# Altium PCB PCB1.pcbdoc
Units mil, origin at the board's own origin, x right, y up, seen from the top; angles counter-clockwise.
Board outline 7016.85 x 5604.57 mil, 2 copper layers (Top Layer, Bottom Layer); 46 components, 30 nets, 160 pads, 153 vias.
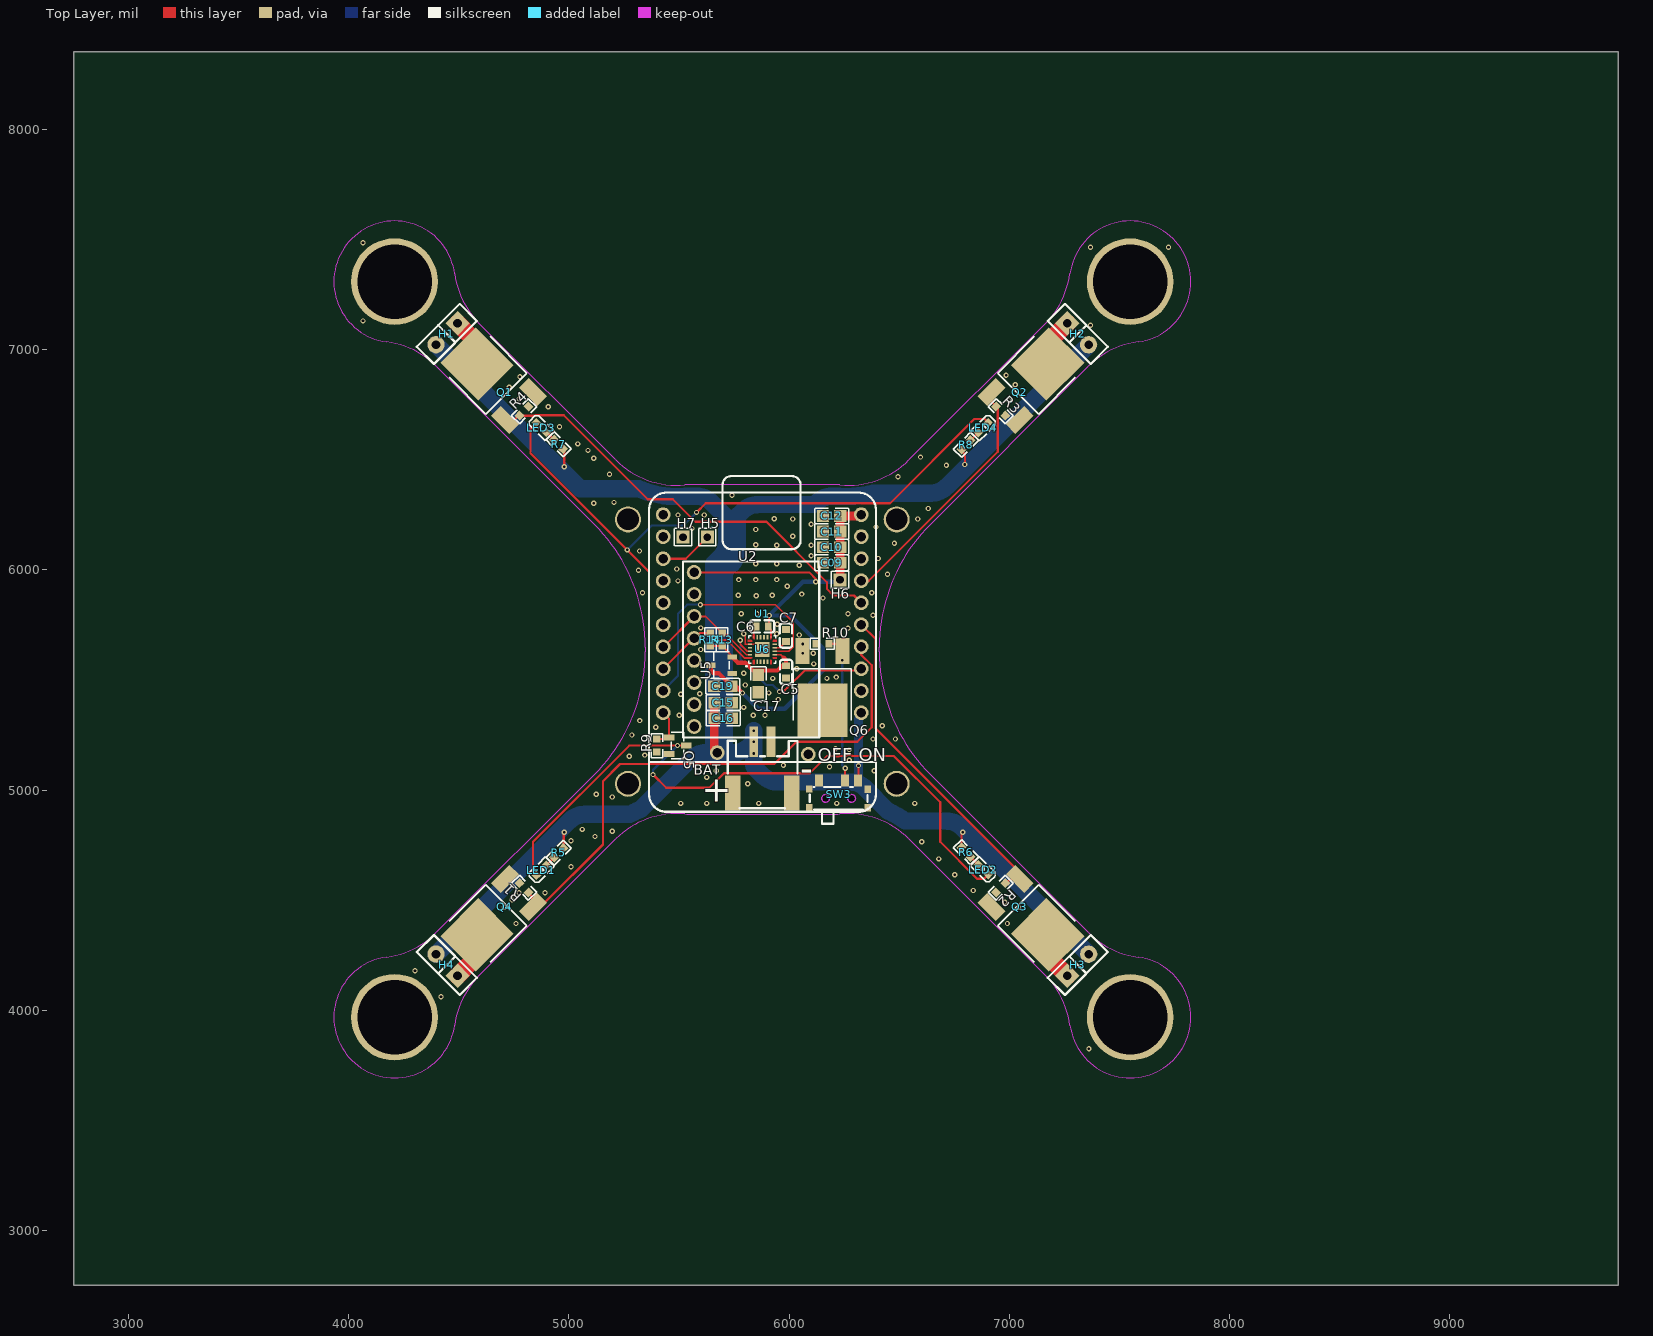
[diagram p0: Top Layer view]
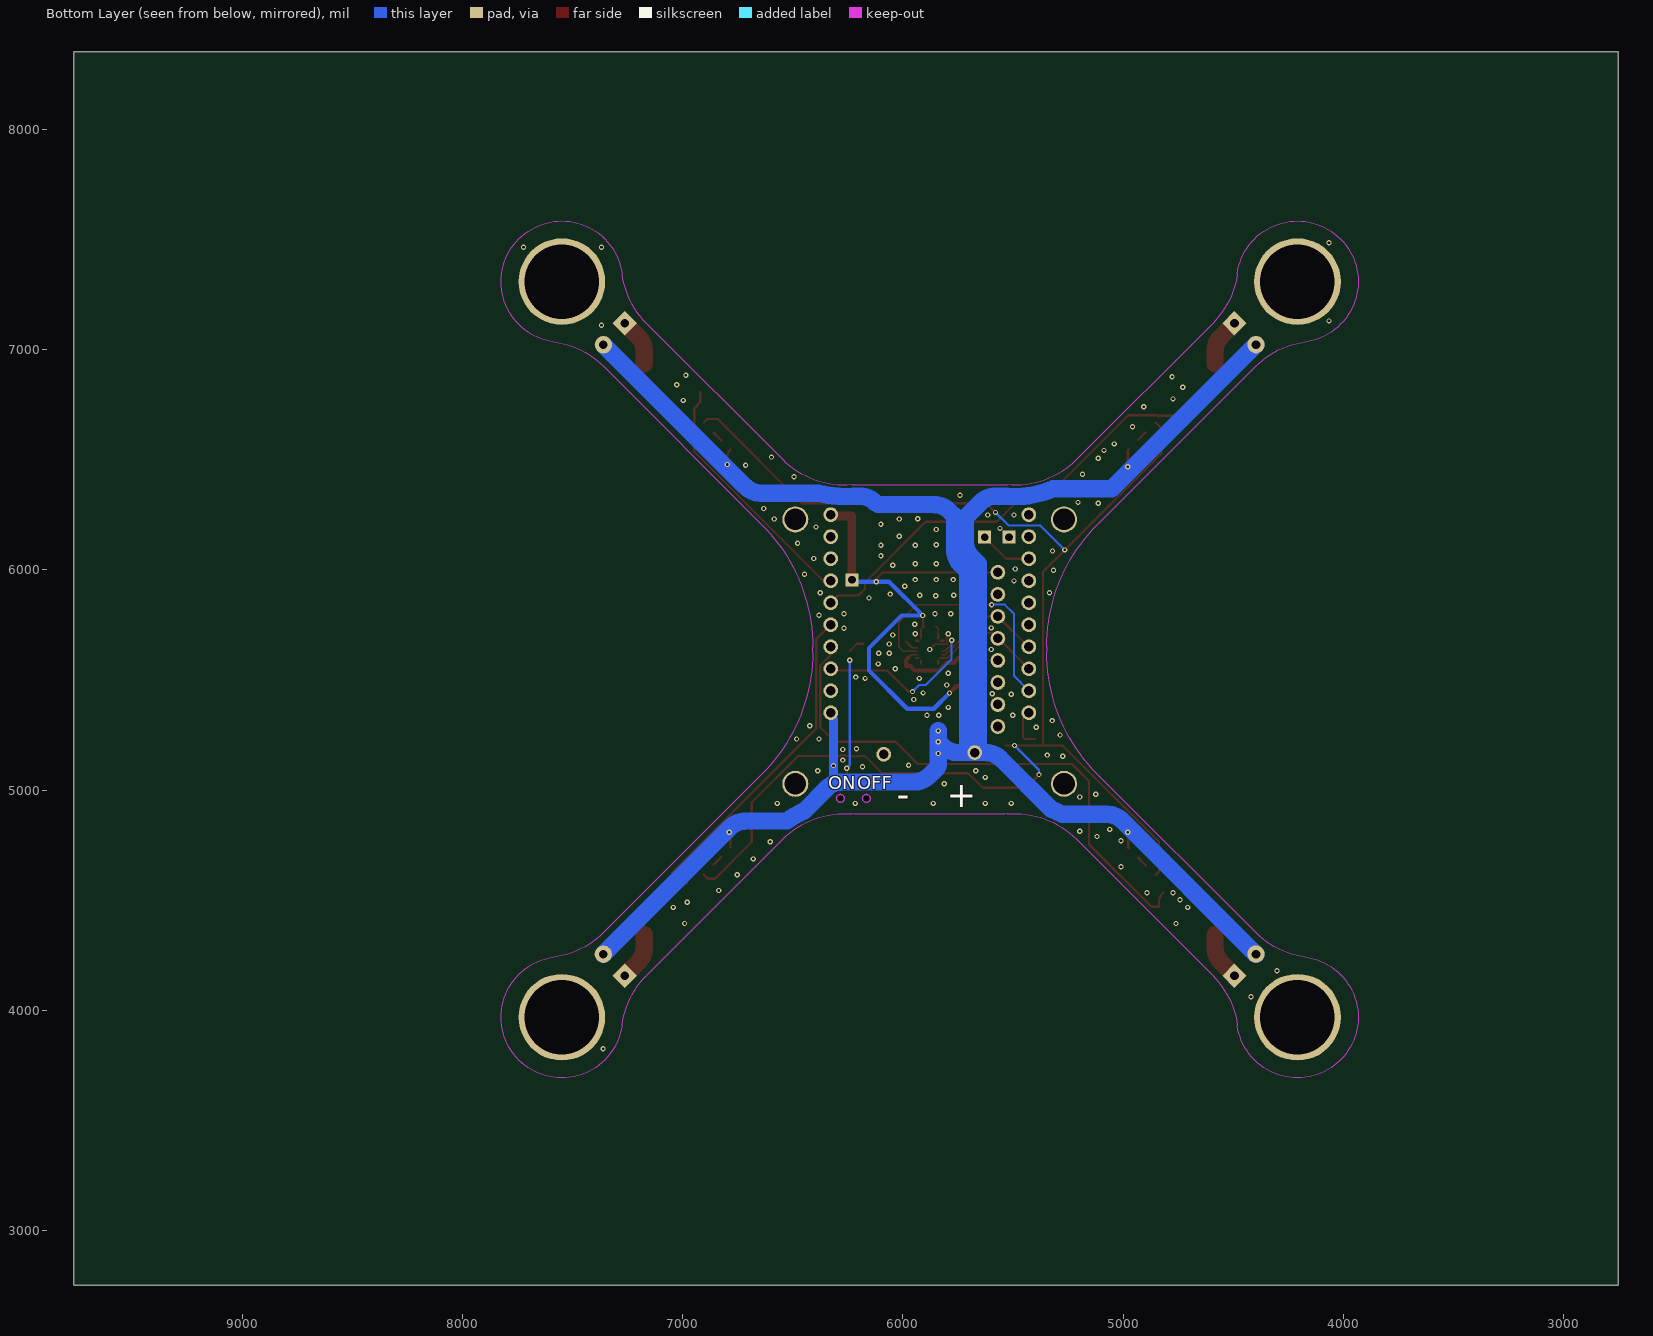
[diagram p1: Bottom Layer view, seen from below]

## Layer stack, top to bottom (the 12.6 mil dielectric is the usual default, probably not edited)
Top Layer: signal copper (thickness not stored)
Dielectric: dielectric 12.6, FR-4, Dk 4.8
Bottom Layer: signal copper (thickness not stored)

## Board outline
9766.85,2750 2750,2750 2750,8354.57 9766.85,8354.57

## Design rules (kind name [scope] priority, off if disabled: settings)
BoardOutlineClearance copperThickness1oz [All] p0: genericclearance=10 ignorepadtopadclearanceinfootprint=FALSE except(0: Arc-SplitContinuation Track-SplitContinuation SMDPad-SplitContinuation THPad-SplitContinuation Via-SplitContinuation Fill-SplitContinuation Poly-SplitContinuation Region-SplitContinuation Text-SplitContinuation; 6: Track-CutoutEdge SMDPad-CutoutEdge THPad-CutoutEdge Via-CutoutEdge Region-CutoutEdge; 11.8: Track-OutlineEdge SMDPad-OutlineEdge THPad-OutlineEdge Via-OutlineEdge Fill-OutlineEdge Region-OutlineEdge Poly-OutlineEdge Text-OutlineEdge Fill-CutoutEdge)
BoardOutlineClearance copperThickness2oz [All] p0: genericclearance=10 ignorepadtopadclearanceinfootprint=FALSE except(0: Arc-SplitContinuation Track-SplitContinuation SMDPad-SplitContinuation THPad-SplitContinuation Via-SplitContinuation Fill-SplitContinuation Poly-SplitContinuation Region-SplitContinuation Text-SplitContinuation; 6: Track-CutoutEdge SMDPad-CutoutEdge THPad-CutoutEdge Via-CutoutEdge Region-CutoutEdge; 11.8: Track-OutlineEdge SMDPad-OutlineEdge THPad-OutlineEdge Via-OutlineEdge Fill-OutlineEdge Region-OutlineEdge Poly-OutlineEdge Text-OutlineEdge Fill-CutoutEdge)
Clearance copperThickness1oz [(InNet('+VBAT') OR InNet('$1N990') OR InNet('$1N1042') OR InNet('$1N1143') OR InNet('$1N1147') OR InNet('GND') OR InNet('B-') OR InNet('+3.3V') OR InNet('SCL') OR InNet('SDA') OR InNet('P01') OR InNet('P05') OR InNet('P06') OR InNet('P04') OR InNet('P07') OR InNet('P08') OR InNet('P09') OR InNet('RX') OR InNet('$1N3735') OR InNet('$1N3774') OR InNet('$1N3813') OR InNet('$1N3852') OR InNet('$1N5655') OR InNet('$1N11155') OR InNet('$1N12497') OR InNet('1.8V') OR InNet('$2N590') OR InNet('P00') OR InNet('XDA') OR InNet('XCL'))] p1: gap=7 ignorepadtopadclearanceinfootprint=FALSE except(4: Track-Track; 6: Track-SMDPad SMDPad-SMDPad Track-THPad SMDPad-THPad THPad-THPad Track-Via SMDPad-Via THPad-Via Via-Via SMDPad-Fill THPad-Fill Via-Fill Fill-Fill Track-Region SMDPad-Region THPad-Region Via-Region Region-Region Track-Poly SMDPad-Poly THPad-Poly Via-Poly Fill-Poly Region-Poly Poly-Poly Track-Text SMDPad-Text THPad-Text Via-Text Fill-Text Region-Text Poly-Text Text-Text; 6.9: Track-Hole SMDPad-Hole THPad-Hole Via-Hole Fill-Hole Region-Hole Poly-Hole Text-Hole Sheet-Hole; 11.8: Track-Fill Fill-Region Track-Sheet SMDPad-Sheet THPad-Sheet Via-Sheet Fill-Sheet Region-Sheet Poly-Sheet Text-Sheet)
Clearance copperThickness2oz [All] p1: gap=7 ignorepadtopadclearanceinfootprint=FALSE except(6: Track-SMDPad SMDPad-SMDPad Track-THPad SMDPad-THPad THPad-THPad Track-Via SMDPad-Via THPad-Via Via-Via SMDPad-Fill THPad-Fill Via-Fill Fill-Fill Track-Region SMDPad-Region THPad-Region Via-Region Region-Region Track-Poly SMDPad-Poly THPad-Poly Via-Poly Fill-Poly Region-Poly Poly-Poly Track-Text SMDPad-Text THPad-Text Via-Text Fill-Text Region-Text Poly-Text Text-Text; 6.9: Track-Hole SMDPad-Hole THPad-Hole Via-Hole Fill-Hole Region-Hole Poly-Hole Text-Hole Sheet-Hole; 8: Track-Track; 11.8: Track-Fill Fill-Region Track-Sheet SMDPad-Sheet THPad-Sheet Via-Sheet Fill-Sheet Region-Sheet Poly-Sheet Text-Sheet)
DiffPairsRouting differentialPair [All] p1: maxuncoupledlength=10 minlimit=6 maxlimit=6 mostfreqgap=6 toplayer_minwidth=5 toplayer_prefwidth=10 toplayer_maxwidth=100 bottomlayer_minwidth=5 bottomlayer_prefwidth=10 bottomlayer_maxwidth=100
PasteMaskExpansion pasteMaskExpansion [All] p1: expansion=0
PlaneConnect innerPlane [All] p1: planeconnectstyle=Relief reliefexpansion=20 reliefentries=4 reliefconductorwidth=10 reliefairgap=10
PolygonConnect copperRegion [All] p1: connectstyle=Relief reliefentries=4 reliefconductorwidth=10 polygonreliefangle="90 Angle" airgapwidth=10
PolygonConnect solid [All] p1: connectstyle=Direct reliefentries=4 reliefconductorwidth=10 polygonreliefangle="90 Angle" airgapwidth=10
RoutingVias viaSize [All] p1: viastyle="Through Hole" holewidth=12.0078 minholewidth=11.811 maxholewidth=248.0314 width=24.0158 minwidth=19.685 maxwidth=393.7008
SolderMaskExpansion solderMaskExpansion [All] p1: useseparateexpansions=TRUE expansion=2 expansionbottom=2
Width copperThickness1oz [All] p1: maxlimit=100 minlimit=5 preferedwidth=10
Width copperThickness2oz [All] p1: maxlimit=100 minlimit=8 preferedwidth=10

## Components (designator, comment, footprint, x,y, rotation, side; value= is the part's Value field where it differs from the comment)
BAT "HX PH2.0-2PWT" CONN-SMD_2P-P2.00 5878.43,5103.62 r0 top
C5 "CC0603KRX7R9BB104" C0603 5986.14,5537.32 r90 top
C6 "CC0603KRX7R9BB104" C0603 5877.75,5743.69 r0 top
C7 "CC0603KRX7R9BB104" C0603 5985.46,5701.8 r270 top
C09 "JMK212BJ476MG-T" C0805 6193.39,6032.76 r0 top
C10 "JMK212BJ476MG-T" C0805 6193.39,6103.62 r0 top
C11 "JMK212BJ476MG-T" C0805 6193.39,6174.49 r0 top
C12 "JMK212BJ476MG-T" C0805 6193.39,6245.35 r0 top
C15 "JMK212BJ476MG-T" C0805 5700,5397.09 r180 top
C16 "JMK212BJ476MG-T" C0805 5700,5327.09 r180 top
C17 "JMK212BJ476MG-T" C0805 5860.47,5483.46 r90 top
C19 "JMK212BJ476MG-T" C0805 5698.9,5471.5 r0 top
H1 "KF332J-3.5-2P BLACK" HDR-TH_2P-P3.50-V-M_1 4445.35,7072.13 r225 top
H2 "KF332J-3.5-2P BLACK" HDR-TH_2P-P3.50-V-M_1 7311.5,7072.13 r315 top
H3 "KF332J-3.5-2P BLACK" HDR-TH_2P-P3.50-V-M_1 7311.5,4205.98 r45 top
H4 "KF332J-3.5-2P BLACK" HDR-TH_2P-P3.50-V-M_1 4445.35,4205.98 r135 top
H5 "TMM-101-01-G-S" HDR-TH_TMM-101-06-L-S 5628.43,6149.06 r0 top
H6 "TMM-101-01-G-S" HDR-TH_TMM-101-06-L-S 6231.42,5955.35 r0 top
H7 "TMM-101-01-G-S" HDR-TH_TMM-101-06-L-S 5518.43,6149.06 r0 top
LED1 "XL-1608SURC-06" LED0603-RD_RED 4874.64,4636.55 r45 top
LED2 "XL-1608SURC-06" LED0603-RD_RED 6882.36,4639.05 r135 top
LED3 "PSC-1608U50GC-G4" LED0603-RD_GREEN 4874.49,6646.93 r315 top
LED4 "PSC-1608U50GC-G4" LED0603-RD_GREEN 6882.36,6646.93 r225 top
Q1 "100N03A" TO-252-2_L6.6-W6.1-P4.57-LS9.9-BR-CW 4677.64,6839.84 r315 top
Q2 "100N03A" TO-252-2_L6.6-W6.1-P4.57-LS9.9-BR-CW 7079.21,6839.84 r225 top
Q3 "100N03A" TO-252-2_L6.6-W6.1-P4.57-LS9.9-BR-CW 7079.21,4438.27 r135 top
Q4 "100N03A" TO-252-2_L6.6-W6.1-P4.57-LS9.9-BR-CW 4677.64,4438.27 r45 top
Q5 "SI2302-HXY" SOT-23-3_L2.9-W1.3-P1.90-LS2.4-BR 5493.78,5202.45 r180 top
Q6 "100N03A" TO-252-2_L6.6-W6.1-P4.57-LS9.9-BR-CW 6151.57,5497.4 r90 top
R1 "0603WAF1002T5E" R0603 4795.75,4556.38 r135 top
R2 "0603WAF1002T5E" R0603 6961.1,4556.38 r225 top
R3 "0603WAF1002T5E" R0603 6961.1,6721.73 r315 top
R4 "0603WAF1002T5E" R0603 4795.75,6721.73 r45 top
R5 "0603WAF4700T5E" R0603 4953.38,4715.29 r45 top
R6 "0603WAF4700T5E" R0603 6803.62,4717.79 r135 top
R7 "0603WAF4700T5E" R0603 4953.03,6570.75 r315 top
R8 "0603WAF4700T5E" R0603 6803.62,6568.19 r225 top
R9 "0603WAF1002T5E" R0603 5399.29,5202.45 r270 top
R10 "0603WAF1002T5E" R0603 6151.57,5664.96 r180 top
R13 "0603WAF1002T5E" R0603 5695.91,5683.94 r270 top
R14 "0603WAF1002T5E" R0603 5642.05,5683.94 r270 top
SW3 "MK-12C03-G015" SW-SMD_MK-12C03-G015 6224.88,4981.57 r0 top
U1 "NanoCell" NanoCell 6417.8,6371.34 r270 top
U2 "MPU-6050 module" "MPU-6050 module" 5568.43,5989.06 r0 top
U5 "XC6206P182MR_C22466430" SOT-23-3_L2.9-W1.6-P1.90-LS2.8-BR 5692.91,5567.24 r0 top
U6 "ICM-20948" QFN-24_L3.0-W3.0-P0.40-BL-EP 5878.4,5639 r0 top

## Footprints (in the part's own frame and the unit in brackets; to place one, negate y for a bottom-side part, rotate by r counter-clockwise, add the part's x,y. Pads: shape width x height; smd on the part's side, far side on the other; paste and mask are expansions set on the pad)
C0603 [mm]
  rect 0.8x0.9 smd: 1(-0.7,0) 2(0.7,0)
  silkscreen extent -1.39,-0.71 1.39,0.71
C0805 [mm]
  rect 1.41x1.35 smd: 1(-1,0) 2(1,0)
  silkscreen extent -1.96,-0.9 1.96,0.9
CONN-SMD_2P-P2.00 [mm]
  rect 1x3.5 smd: 1(1,2.954) 2(-1,2.954)
  rect 1.8x4 smd: 3(-3.412,-2.954) 4(3.412,-2.954)
  silkscreen extent -4,-4.73 4.06,3.07
HDR-TH_2P-P3.50-V-M_1 [mm]
  rect 2x2 hole 1: 1(-1.75,0)
  round 2 hole 1: 2(1.76,-0.005)
  silkscreen extent -3.5,-1.4 3.5,1.4
HDR-TH_TMM-101-06-L-S [mm]
  rect 1.5x1.5 hole 0.89: 1(0,0)
  silkscreen extent -1,-1 1,1
LED0603-RD_GREEN [mm]
  rect 0.8x0.8 smd: 1(-0.799,-0.003) 2(0.799,0.003)
  silkscreen extent -1.49,-0.75 1.39,0.76
LED0603-RD_RED [mm]
  rect 0.8x0.8 smd: 1(-0.8,-0.003) 2(0.8,0.003)
  silkscreen extent -1.49,-0.75 1.39,0.76
"MPU-6050 module" [mm]
  round 1.7 hole 1.1: 1(0,0) 2(0,-2.54) 3(0,-5.08) 4(0,-7.62) 5(0,-10.16) 6(0,-12.7) 7(0,-15.24) 8(0,-17.78)
  silkscreen extent -1.27,-19.05 14.43,1.27
NanoCell [mm]
  round 1.7 hole 1.1: 1(25.908,-2.286) 2(23.368,-2.286) 3(20.828,-2.286) 4(18.288,-2.286) 5(15.748,-2.286) 6(13.208,-2.286) 7(10.668,-2.286) 8(8.128,-2.286) 9(5.588,-2.286) 10(3.048,-2.286) 11(3.048,-25.146) 12(5.588,-25.146) 13(8.128,-25.146) 14(10.668,-25.146) 15(13.208,-25.146) 16(15.748,-25.146) 17(18.288,-25.146) 18(20.828,-25.146) 19(23.368,-25.146) 20(25.908,-25.146)
  silkscreen extent -1.4,-26.76 37.33,-0.6
QFN-24_L3.0-W3.0-P0.40-BL-EP [mm]
  round 0.04 smd: 1(-1,-1.427) 6(1,-1.427) 7(1.427,-1) 12(1.427,1) 13(1,1.427) 18(-1,1.427) 19(-1.427,1) 24(-1.427,-1)
  rect 0.2x0.505 smd: 2(-0.6,-1.427) 3(-0.2,-1.427) 4(0.2,-1.427) 5(0.6,-1.427) 14(0.6,1.427) 15(0.2,1.427) 16(-0.2,1.427) 17(-0.6,1.427)
  rect 0.505x0.2 smd: 8(1.427,-0.6) 9(1.427,-0.2) 10(1.427,0.2) 11(1.427,0.6) 20(-1.427,0.6) 21(-1.427,0.2) 22(-1.427,-0.2) 23(-1.427,-0.6)
  rect 1.7x1.7 smd: 25(0,0)
  Top Layer region: -1.1,1.68 -0.9,1.68 -0.9,1.175 -1,1.174 -1.1,1.274
  Top Layer region: -1.68,-1.1 -1.68,-0.9 -1.175,-0.9 -1.174,-1 -1.274,-1.1
  Top Layer region: 1.68,-1.1 1.275,-1.1 1.175,-1 1.175,-0.9 1.68,-0.9
  Top Layer region: 1.68,1.1 1.68,0.9 1.175,0.9 1.174,1 1.274,1.1
  Top Layer region: 1.1,1.68 1.1,1.274 1,1.174 0.9,1.175 0.9,1.68
  Top Layer region: -1.1,-1.68 -1.1,-1.275 -1,-1.174 -0.9,-1.175 -0.9,-1.68
  Top Layer region: 1.1,-1.68 0.9,-1.68 0.9,-1.175 1,-1.175 1.1,-1.275
  Top Layer region: -1.68,1.1 -1.274,1.1 -1.174,1 -1.175,0.9 -1.68,0.9
  silkscreen extent -1.89,-2 1.58,1.58
R0603 [mil]
  rect 31.75x34.02 smd: 1(-29.66,0) 2(29.66,0)
  silkscreen extent -55,-26 55,26
SOT-23-3_L2.9-W1.3-P1.90-LS2.4-BR [mm]
  rect 1.25x0.7 smd: 1(1,-0.95) 2(1,0.95) 3(-1,0)
  silkscreen extent -0.73,-1.53 0.73,1.53
SOT-23-3_L2.9-W1.6-P1.90-LS2.8-BR [mm]
  rect 1.07x0.6 smd: 1(1.235,-0.95) 2(1.235,0.95) 3(-1.235,0)
  silkscreen extent -0.88,-1.54 0.88,1.54
SW-SMD_MK-12C03-G015 [mm]
  rect 0.9x1.4 smd: 1(-2.25,1.559) 2(0.75,1.559) 3(2.25,1.559)
  rect 0.75x0.85 smd: 4(-3.375,0.592) 5(-3.375,-1.559) 6(3.375,0.567) 7(3.375,-1.558)
  Board Outline Layer circle w0.005: c1.5,-0.483 r0.45
  Board Outline Layer circle w0.005: c-1.5,-0.484 r0.45
  Board Outline Layer region: 1.95,-0.483 1.905,-0.679 1.78,-0.835 1.6,-0.922 1.4,-0.922 1.219,-0.835 1.094,-0.679 1.05,-0.483 1.05,-0.483 1.094,-0.288 1.219,-0.132 1.4,-0.045 1.6,-0.045 1.78,-0.132 1.905,-0.288 1.95,-0.483
  Board Outline Layer region: -1.05,-0.484 -1.095,-0.679 -1.22,-0.835 -1.4,-0.922 -1.6,-0.922 -1.781,-0.835 -1.906,-0.679 -1.95,-0.484 -1.95,-0.484 -1.906,-0.288 -1.781,-0.132 -1.6,-0.045 -1.4,-0.045 -1.22,-0.132 -1.095,-0.288 -1.05,-0.484
  Multi-Layer board cut-out: 1.95,-0.483 1.905,-0.679 1.78,-0.835 1.6,-0.922 1.4,-0.922 1.219,-0.835 1.094,-0.679 1.05,-0.483 1.05,-0.483 1.094,-0.288 1.219,-0.132 1.4,-0.045 1.6,-0.045 1.78,-0.132 1.905,-0.288 1.95,-0.483
  Multi-Layer board cut-out: -1.05,-0.484 -1.095,-0.679 -1.22,-0.835 -1.4,-0.922 -1.6,-0.922 -1.781,-0.835 -1.906,-0.679 -1.95,-0.484 -1.95,-0.484 -1.906,-0.288 -1.781,-0.132 -1.6,-0.045 -1.4,-0.045 -1.22,-0.132 -1.095,-0.288 -1.05,-0.484
  silkscreen extent -3.33,-3.41 3.32,0.82
TO-252-2_L6.6-W6.1-P4.57-LS9.9-BR-CW [mm]
  rect 3x1.6 smd: 1(3.424,-2.29) 3(3.424,2.29)
  rect 6.2x5.8 smd: 2(-3.424,0)
  silkscreen extent -4.58,-3.35 1.38,3.35

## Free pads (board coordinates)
  round 393.7 hole 338.58: 1(4207.86,7309.62) 2(7548.99,7309.62) 3(4207.86,3968.49) 4(7548.99,3968.49)
  round 118.11 hole 98.43: 1(5268.19,5028.82) 1(5268.19,6229.61) 1(6488.66,5028.82) 1(6488.66,6229.61)
  round 66.93 hole 43.31: 1(5673.7,5170.55) 2(6087.09,5162.68)

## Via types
v1: diameter 24.02, hole 12.01, Top Layer to Bottom Layer, 153 vias

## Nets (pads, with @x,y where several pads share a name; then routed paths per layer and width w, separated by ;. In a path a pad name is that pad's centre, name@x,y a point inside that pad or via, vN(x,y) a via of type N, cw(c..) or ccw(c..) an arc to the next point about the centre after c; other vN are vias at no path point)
1.8V: C5.2 C17.2 R13.2 R14.2 U5.2 U6.8 | length 489.2
  Top Layer w7.87: U6.8 5961.94,5615.38 5975.65,5601.67
  Top Layer w10: R14.2 R13.2 5741.54,5608.64 U5.2
  Top Layer w19.68: U5.2 5766.97,5579.21 5800.63,5579.21 5836.54,5543.31 5946.77,5543.31 5968.35,5564.88 C5.2 5986.14,5591.18 5975.65,5601.67
$1N990: H3.1 Q3.2 | length 217.9
  Top Layer w78.74: Q3.2 7174.53,4286.94 ccw(c7274.53,4286.94) 7203.82,4216.22 H3.1
$1N1042: H4.1 Q4.2 | length 217.9
  Top Layer w78.74: H4.1 4553.03,4216.22 ccw(c4482.32,4286.94) 4582.32,4286.94 Q4.2
$1N1143: H1.1 Q1.2 | length 217.9
  Top Layer w78.74: H1.1 4553.03,7061.89 cw(c4482.32,6991.17) 4577.26,7022.58 cw(c4482.32,6991.17) 4582.32,6991.17 Q1.2
$1N1147: H2.1 Q2.2 | length 217.9
  Top Layer w78.74: Q2.2 7174.53,6991.17 cw(c7274.53,6991.17) 7203.82,7061.89 H2.1
$1N3735: LED1.2 R5.1 | length 50.3
  Top Layer w10: LED1.2 4932.07,4694.18 cw(c4932.4,4693.85) R5.1
$1N3774: LED2.2 R6.1 | length 50.3
  Top Layer w10: R6.1 ccw(c6825.06,4696.82) 6824.73,4696.49 LED2.2
$1N3813: LED3.2 R7.1 | length 48.7
  Top Layer w10: LED3.2 cw(c4896.84,6619.54) 4900.54,6623.24 R7.1
$1N3852: LED4.2 R8.1 | length 50.3
  Top Layer w10: R8.1 ccw(c6824.6,6589.63) 6824.93,6589.3 LED4.2
$1N5655: LED1.1 LED2.1 LED3.1 LED4.1 Q5.3 | length 6759.1
  Top Layer w10: LED3.1 4825.2,6642.15 4825.2,6530.71 v1(5264.79,6091.11) 5363.78,5992.13 5363.78,5202.89 5363.09,5202.2 ; LED1.1 4837.17,4629.49 4837.17,4765.35 5274.02,5202.2 5363.09,5202.2 ; v1(5381.73,5070.55) 5441.57,5010.71 5637.76,5010.71 5704.09,5077.05 6094.37,5077.05 6171.65,5154.33 6205.51,5154.33 6206.93,5152.91 6225.98,5152.91 6227.4,5154.33 6258.82,5154.33 6263.86,5159.37 6282.91,5159.37 6287.95,5154.33 6476.85,5154.33 6686.3,4944.88 6686.3,4765.35 6853.86,4597.8 6885.63,4597.8 LED2.1 ; Q5.3 5532.91,5202.2 5363.09,5202.2 ; v1(5579.21,6261.42) 5621.1,6303.31 6458.9,6303.31 6841.89,6686.3 6887.51,6686.3 LED4.1
  Bottom Layer w10: v1@5268.03,6093.86 5375.75,6201.57 5519.37,6201.57 v1(5579.21,6261.42) ; v1(5381.73,5070.55) 5381.73,5091.09 v1(5493.09,5202.45)
$1N11155: BAT.1 Q6.2
$1N12497: Q6.1 R10.1 SW3.2 | length 626.7
  Top Layer w10: R10.1 6208.98,5664.96 Q6.1 ; SW3.2 v1(6254.41,5099.9)
  Bottom Layer w10: v1(6241.73,5590.32) 6241.73,5112.57 v1(6254.41,5099.9)
$2N590: C7.2 U6.10 | length 62.2
  Top Layer w7.87: U6.10 5958.09,5646.87 C7.2
+3.3V: C6.2 C09.2 C10.2 C11.2 C12.2 C19.2 H6.1 U1.10 U2.1 U5.3 U6.13 | length 2545.1
  Top Layer w7.87: C6.2 5917.77,5731.23 U6.13
  Top Layer w10: U2.1 6090.94,5989.06 6120.71,5959.29 v1(6120.71,5946.69) ; C6.2 5909.24,5747.63 v1(5909.24,5792.96)
  Top Layer w19.68: U5.3 5644.29,5544.06 5658.21,5530.14 5680.94,5530.14 5738.27,5472.82 C19.2 5757.99,5471.5 v1(5788.29,5441.2)
  Top Layer w39.37: H6.1 ccw(c6228.19,5958.59) 6232.76,5958.59 C09.2 C10.2 C11.2 C12.2 6313.35,6245.35 ccw(c6313.35,6265.79) U1.10
  Bottom Layer w19.68: v1(5788.29,5441.2) 5859.72,5369.76 5980.16,5369.76 6153.7,5543.31 6153.7,5645.04 6005.78,5792.96 v1(5909.24,5792.96) 6062.98,5946.69 v1(6120.71,5946.69) 6226.99,5946.69 6228.43,5948.13 cw(c6238.64,5948.13) H6.1
+VBAT: BAT.2 C15.2 C16.2 H1.2 H2.2 H3.2 H4.2 pad.1@5673.7,5170.55 R5.2 R6.2 R7.2 R8.2 SW3.3 U1.1 | length 10472
  Top Layer w10: R7.2 cw(c4963.32,6539.1) 4978.43,6539.1 v1(4978.43,6469.06) ; R5.2 ccw(c4974.35,4739.35) 4976.54,4737.16 4976.53,4807.16 v1(4978.43,4809.06) ; SW3.3 ccw(c6308.69,5047.71) 6315.43,5047.71 v1(6315.43,5111.5) ; R6.2 6782.65,4795.11 cw(c6802.37,4795.11) v1(6788.43,4809.06) ; R8.2 cw(c6744.56,6509.13) 6798.43,6509.13 v1(6798.43,6479.06)
  Top Layer w39.37: C15.2 C16.2 5660.63,5183.62 pad.1@5673.7,5170.55
  Bottom Layer w39.37: 6315.6,5029.36 cw(c6316.39,5030.15) 6315.28,5030.15 6315.28,5321.11 cw(c6358.02,5321.11) U1.1
  Bottom Layer w78.74: H4.2@4396.64,4254.7 5002.41,4860.48 cw(c5073.12,4789.77) 5073.12,4889.77 5276.77,4889.77 cw(c5490.73,4499.71) 5325.88,4912.92 5554.22,5141.26 cw(c5624.93,5070.55) 5624.93,5170.55 pad.1@5673.7,5170.55 ; H1.2@4396.64,7023.41 5050.92,6369.13 5316.32,6369.13 ccw(c5490.73,6778.4) 5450.47,6335.34 ccw(c5490.73,6778.4) 5530.69,6335.32 cw(c5543.82,6190.18) 5530.99,6335.34 5577.57,6335.34 cw(c5577.57,6235.34) 5648.28,6306.05 5716.85,6237.48 5716.85,6129.3 cw(c5616.85,6129.3) 5687.56,6058.58 5657.01,6028.03 5657.01,5210.85 ccw(c5714,5210.85) pad.1@5673.7,5170.55 ; v1(5839.06,5268.98) v1(5839.06,5219.92) ; 6111.81,6297.32 5860,6297.32 ccw(c5860,6197.32) 5789.29,6268.03 5764.72,6243.46 5764.72,6093.39 cw(c5664.72,6093.39) 5735.44,6022.68 5704.88,5992.13 5704.88,5187.45 ccw(c5728.79,5187.45) 5705.93,5180.44 ccw(c5728.79,5187.45) 5711.88,5170.55 ; 6125.4,6306.03 cw(c6196.11,6235.32) 6196.11,6335.32 6226.16,6335.32 ccw(c6266.12,6778.4) 6382.67,6349.06 6644.44,6349.06 ccw(c6644.44,6449.06) 6715.15,6378.34 H2.2@7360.21,7023.41 ; H3.2@7360.21,4254.7 6784.44,4830.48 ccw(c6713.73,4759.77) 6713.73,4859.77 6527.43,4859.77 ccw(c6266.12,4499.71) 6448.76,4905.37 6344,5010.14 ccw(c6279.89,4946.03) 6315.6,5029.36 ccw(c6279.89,4946.03) 6279.89,5036.69 5951.34,5036.69 cw(c5951.34,5136.69) 5880.63,5065.98 5846.93,5099.69 cw(c5865.94,5118.69) 5839.06,5118.69 v1(5839.06,5166.61) v1(5839.06,5219.92) ; pad.1@5673.7,5170.55 5711.88,5170.55 ; 5711.88,5170.55 5748.26,5170.55 ccw(c5748.26,5270.55) 5814.05,5195.24 ccw(c5748.26,5270.55) 5818.97,5199.84 v1(5839.06,5219.92)
B-: U1.2
GND: C5.1 C6.1 C7.1 C09.1 C10.1 C11.1 C12.1 C15.1 C16.1 C17.1 C19.1 H7.1 pad.2@6087.09,5162.68 Q1.3 Q2.3 Q3.3 Q4.3 Q5.2 Q6.3 R1.2 R2.2 R3.2 R4.2 R9.2 R10.2 U1.12 U2.2 U5.1 U6.18 U6.20 U6.25 | length 191.2
  Top Layer w7.87: v1(5794.65,5710.87) 5800.63,5704.88 5800.63,5662.99 5801,5662.62 U6.20 5854.78,5662.62 v1(5878.4,5639) ; U6.18 5839.03,5732.54 C6.1
  other v1: 7361.79,3825.11 4418.81,4061.33 4300.7,4179.44 4759.37,4394.33 6991.5,4394.33 4706.61,4467.24 7043.23,4467.24 6979.53,4490.08 4741.42,4502.05 4773.14,4533.77 4891.25,4533.77 6835.91,4543.94 6752.13,4615.75 5009.36,4651.88 6680.31,4687.56 6602.52,4765.35 5009.36,4769.99 5118.43,4789.29 5196.22,4813.23 5060.94,4821.57 5507.8,4939.68 5625.91,4939.68 5862.13,4939.68 6216.46,4939.68 6570.79,4939.68 5196.22,4968.82 5124.41,4980.79 5812.6,5028.66 5625.91,5057.8 5668.98,5088.5 6387.09,5088.5 6183.62,5106.46 5974.17,5112.44 6273.39,5136.38 5274.02,5154.33 5344.33,5159.11 6273.39,5184.25 6210.47,5187.87 6381.1,5232.13 6482.83,5232.13 5285.98,5250.08 5393.7,5285.98 6422.99,5291.97 5321.89,5315.91 5501.42,5339.84 5836.54,5339.84 5890.39,5339.84 5794.65,5375.75 5950.24,5411.65 5507.4,5435.59 5593.66,5437.64 5908.35,5441.57 5800.63,5477.48 5926.3,5507.4 6171.65,5507.4 6213.54,5513.39 5794.65,5531.34 6034.49,5551.84 6111.81,5573.23 6061.41,5622.07 6109.07,5622.07 5598.52,5639.06 6061.41,5664 6045.98,5704.88 5944.25,5710.87 6267.4,5734.8 5598.43,5736.82 5946.29,5752.95 6381.1,5794.65 5782.68,5800.63 5854.49,5800.63 6267.4,5800.63 6153.7,5872.44 5851.42,5883.08 5769.61,5884.57 5923.62,5884.57 6057.95,5890.39 5333.86,5896.38 6375.12,5896.38 5992.13,5926.3 5495.43,5950.24 5770.71,5956.22 5848.5,5956.22 5944.25,5956.22 6446.93,5980.16 5315.91,5998.11 5489.45,6004.09 6045.98,6022.05 5848.5,6028.03 5944.25,6028.03 6405.04,6051.97 6099.84,6063.94 5320.39,6086.04 5944.25,6111.81 6099.84,6111.81 5848.5,6114.58 6478.27,6120.79 6016.06,6153.7 5848.5,6183.62 5558.94,6188.68 6394.94,6195.2 6099.84,6207.56 6016.06,6231.5 6584.57,6231.5 5932.36,6232.58 5495.43,6249.45 5615.12,6249.45 6632.44,6279.37 5112.44,6303.31 5204.61,6306.79 5740.79,6339.21 6494.8,6422.99 5184.25,6434.96 6714.49,6475.12 5112.44,6506.77 6596.54,6512.76 5086.5,6543.01 5040.63,6572.6 4956.85,6650.39 4906.29,6741.9 6997.48,6770.08 4773.14,6776.93 4729.45,6829.92 7027.4,6841.89 4777.32,6877.8 6985.51,6883.78 7369.18,7111.19 4064.48,7131.26 7369.18,7465.52 7723.51,7465.52 4064.48,7485.59
P00: Q5.1 R9.1 U1.20 | length 180.8
  Top Layer w10: R9.1 5446.67,5232.11 Q5.1 5454.41,5324.72 U1.20
P01: U1.19 U6.9 | length 1155.1
  Top Layer w7.87: v1(5597.17,5842.52) 5938.27,5842.52 6019.06,5761.73 6019.06,5651.02 5999.17,5631.13 U6.9
  Bottom Layer w10: U1.19 5495.43,5518.98 5495.43,5800.63 5537.32,5842.52 v1(5597.17,5842.52)
P04: U1.3 U6.22 | length 813.8
  Top Layer w7.87: v1(5778.7,5680.87) 5778.7,5662.47 5810.03,5631.13 U6.22
  Top Layer w10: v1(5956.22,5447.56) 5974.17,5447.56 5991.18,5464.57 5991.7,5464.57 6070.44,5543.31 6301.81,5543.31 6309.84,5551.34 U1.3
  Bottom Layer w10: v1(5778.7,5680.87) 5778.7,5595.16 5896.38,5477.48 5926.3,5477.48 v1(5956.22,5447.56)
P05: Q4.1 R1.1 U1.4 | length 2500.8
  Top Layer w10: R1.1 cw(c4768.46,4487.14) 4836.71,4487.14 Q4.1 4870.78,4469.84 5154.33,4753.39 5154.33,5040.63 5232.13,5118.43 5310.61,5118.43 5310.87,5118.16 5329.92,5118.16 5330.18,5118.43 5932.28,5118.43 6034.02,5220.16 6309.29,5220.16 6375.12,5285.98 6375.12,5566.88 6327.8,5614.2 U1.4
P06: Q3.1 R2.1 U1.5 | length 1523.1
  Top Layer w10: U1.5 6393.11,5686.02 6393.11,5279.96 7047.64,4625.43 Q3.1 7030.34,4597.34 ccw(c7030.34,4529.09) R2.1
P07: Q1.1 R4.1 U1.6 | length 2016.7
  Top Layer w10: Q1.1@4709.21,6658.67 Q1.1 4726.51,6680.77 ccw(c4726.51,6749.02) R4.1 4846,6700.76 4847.59,6702.35 4976.71,6702.35 5357.8,6321.26 5471.5,6321.26 5574.17,6218.58 5897.32,6218.58 6171.65,5944.25 6171.65,5914.33 6201.57,5884.41 6294.73,5884.41 U1.6
P08: Q2.1 R3.1 U1.7 | length 1145.2
  Top Layer w10: U1.7 6361.81,5951.34 6947.84,6537.37 6947.84,6735 R3.1 6920.14,6762.7 Q2.1
P09: U1.8
RX: H5.1 U1.13 | length 241.1
  Top Layer w10: U1.13 5530.71,6051.34 H5.1
SCL: R13.1 U1.17 U2.3 U6.23 | length 523.1
  Top Layer w7.87: U2.3 5620.45,5789.06 R13.1 5708.14,5713.6 5806.35,5615.38 U6.23
  Top Layer w10: U1.17 ccw(c5427.8,5658.37) 5432.77,5653.4 U2.3
SDA: R14.1 U1.18 U2.4 U6.24 | length 508.5
  Top Layer w7.87: U2.4 5592.97,5713.6 R14.1 5673.28,5682.36 5715.43,5682.36 5798.16,5599.63 U6.24
  Top Layer w10: U1.18 5563.45,5686.99 cw(c5568.43,5682.02) U2.4
XCL: U2.6
XDA: U2.5
pads on no net: BAT.3 BAT.4 SW3.1 SW3.4 SW3.5 SW3.6 SW3.7 U1.9 U1.11 U1.14 U1.15 U1.16 U2.7 U2.8 U6.1 U6.2 U6.3 U6.4 U6.5 U6.6 U6.7 U6.11 U6.12 U6.14 U6.15 U6.16 U6.17 U6.19 U6.21

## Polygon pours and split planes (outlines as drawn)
GND on Bottom Layer (solid, remove dead copper, pour order 6): 5886.3,5316.22 6018.66,5316.22 6018.66,5135.12 5886.3,5135.12
+VBAT on Bottom Layer (solid, remove dead copper, pour order 8): 5640.63,5316.17 5879.17,5316.17 5879.17,5135.12 5640.63,5135.12
+VBAT on Top Layer (solid, remove dead copper, pour order 0): 5621.23,5288.27 5859.29,5288.27 5859.29,5144.32 cw(c5823.05,5136.94) 5858.74,5127.24 5738.39,5127.24 cw(c5660.79,6842.07) 5621.23,5125.95
$1N11155 on Top Layer (solid, remove dead copper, pour order 2): 5896.38,5148.35 5950.24,5148.35 6040,5238.11 6267.4,5238.11 6267.4,5483.46 6040,5483.46 6040,5435.59 5896.38,5291.97
GND on Top Layer (solid, remove dead copper, pour order 4): 3442.83,7966.93 9068.03,7966.93 9516.85,7518.11 9516.85,4172.91 8343.94,3000 4071.18,3000 3000,4071.18 3000,7524.09
GND on Bottom Layer (solid, remove dead copper, pour order 10): 3365.04,8104.57 7536.06,8104.57 8194.33,7446.3 8194.33,3694.17 7595.91,3095.75 4454.17,3095.75 3365.04,4184.88

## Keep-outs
Board Outline Layer:
  lines w3.94: 4171.54,4241.68 ccw(c4119.67,4631.94) 4398.05,4353.56 5116.3,5071.81 ccw(c4559.53,5628.58) 5346.93,5628.58 5346.93,5649.53 ccw(c4559.53,5649.53) 5116.3,6206.3 4398.05,6924.55 ccw(c4119.67,6646.17) 4171.54,7036.43 cw(c4207.86,7309.62) 4481.05,7345.94 ccw(c4871.31,7397.81) 4592.93,7119.43 5212.34,6500.01 ccw(c5490.73,6778.4) 5526.1,6386.29 cw(c5543.78,6190.24) 5543.78,6387.09 6213.07,6387.09 cw(c6213.07,6190.24) 6230.75,6386.29 ccw(c6266.12,6778.4) 6544.51,6500.01 7163.92,7119.43 ccw(c6885.54,7397.81) 7275.8,7345.94 cw(c7548.99,7309.62) 7585.31,7036.43 ccw(c7637.19,6646.17) 7358.8,6924.55 6640.55,6206.3 ccw(c7197.32,5649.53) 6409.92,5649.53 6409.92,5628.58 ccw(c7197.32,5628.58) 6640.55,5071.81 7358.8,4353.56 ccw(c7637.19,4631.94) 7585.31,4241.68 cw(c7548.99,3968.49) 7275.8,3932.17 ccw(c6885.54,3880.3) 7163.92,4158.68 6544.51,4778.1 ccw(c6266.12,4499.71) 6230.75,4891.82 cw(c6213.07,5087.87) 6213.07,4891.02 5543.78,4891.02 cw(c5543.78,5087.87) 5526.1,4891.82 ccw(c5490.73,4499.71) 5212.34,4778.1 4592.93,4158.68 ccw(c4871.31,3880.3) 4481.05,3932.17 cw(c4207.86,3968.49) 4171.54,4241.68

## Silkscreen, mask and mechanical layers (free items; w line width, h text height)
Top Silkscreen Layer:
  text "OFF" at 6129.76,5130.39 h59.06
  text "ON" at 6315.28,5130.39 h59.06
  text "-" at 6051.65,5040.63 h118.11
  text "+" at 5602.83,4946.14 h118.11
Bottom Silkscreen Layer:
  text "OFF" at 6207.56,5004.72 h59.06
  text "ON" at 6339.21,5004.72 h59.06
  text "+" at 5799.69,4922.52 h118.11
  text "-" at 6028.03,4922.52 h118.11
